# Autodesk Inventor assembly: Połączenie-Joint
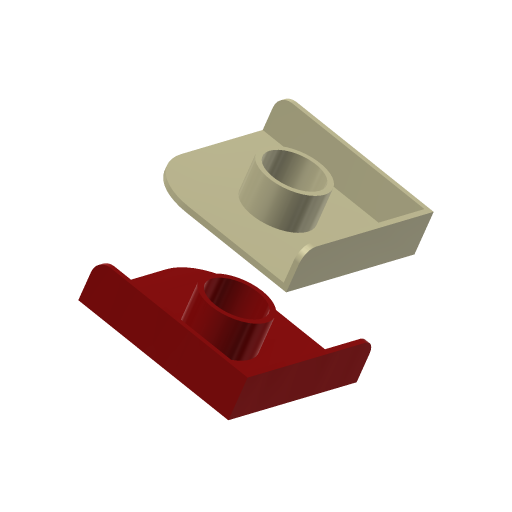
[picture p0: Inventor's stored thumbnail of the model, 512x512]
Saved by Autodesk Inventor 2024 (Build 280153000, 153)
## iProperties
Company: ATC
Shininess: 20.0
Length Units: 11269
Angle Units: 11279
Time Units: 11290
Mass Units: 11283
Length Display Precision: 3
Angle Display Precision: 2
Compacted: True
Created: 2023-03
Part Number: Połączenie-Joint
Document SubType Name: Assembly
Designer: Andrzej Jaskulski
Checked By: A.J.
Engr Approved By: Andrzej Jaskulski
Mfg Approved By: Andrzej Jaskulski
Authority: A.J.
Density: 0.0
Volumn: 0.0
Area: 0.0
PropertySet Name: Model Information
Control State: 0
Master: False
Checked Out: False
Title: A.J.: Kurs R2024-MEP
Author: Andrzej Jaskulski
Revision Number: 1/24
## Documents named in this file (2)
- C:\Users\AndJas\Documents\R2024-MEP\Obszar roboczy\7-Zespół-Para-Połączenie-Joint.iam
- C:\Users\AndJas\Documents\R2024-MEP\Obszar roboczy\ss.ipt
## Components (2 placed, 1 different names)
1. ss:1 — Walcowe:1
2. ss:2 — Walcowe:1
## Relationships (1: CylindricalJoint 1)
- Walcowe:1 [CylindricalJoint]: ss:1 ↔ ss:2
